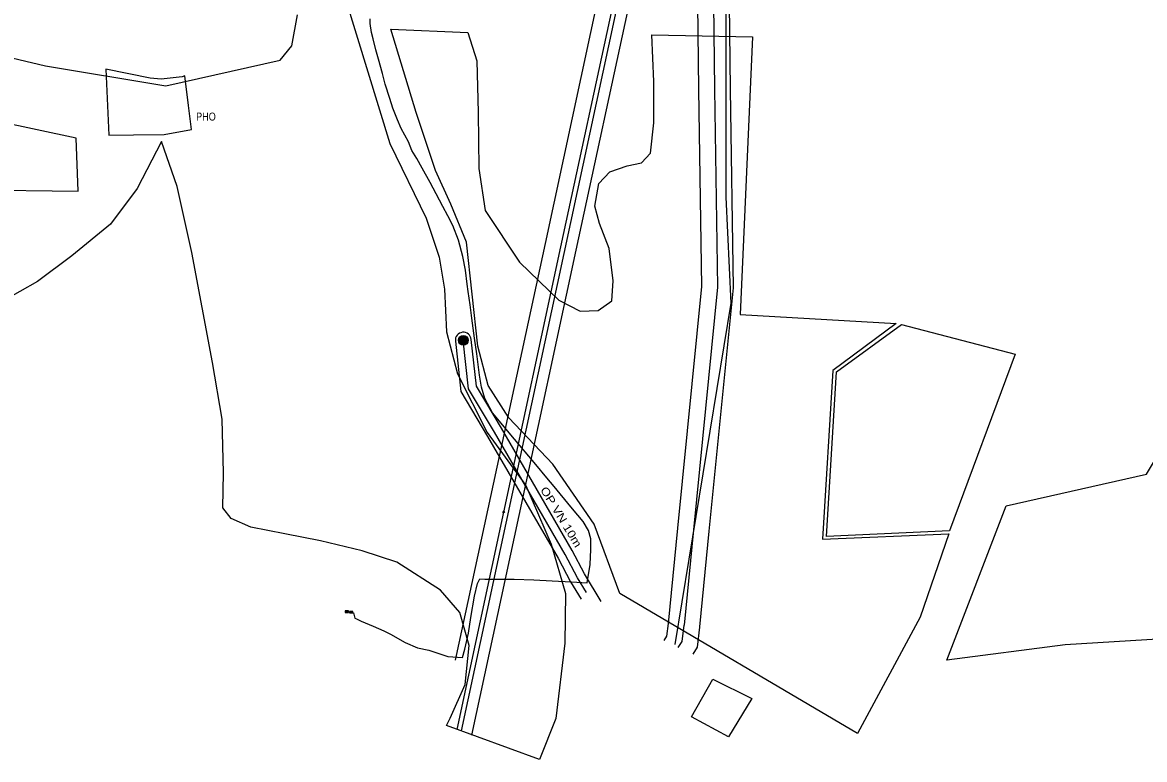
# Model space of a CAD drawing. Extents: x -589836 to -586542, y -1119607 to -1116793.
# Drawn here: x -589106 to -587705, y -1119607 to -1118686 of the extents above; entities that cross this region are included whole.
import ezdxf

# ---------------------------------------------------------------- set-up
doc = ezdxf.new("R2010")
doc.units = 0
doc.header["$LTSCALE"] = 4
doc.header["$PDMODE"] = 32
doc.header["$PDSIZE"] = 2
for name, color, linetype, lineweight in [('18', 7, 'Continuous', 25), ('21', 7, 'Continuous', 25), ('22', 7, 'Continuous', 25), ('25', 7, 'Continuous', 25), ('26', 7, 'Continuous', 25), ('28', 7, 'Continuous', 25), ('29', 7, 'Continuous', 25), ('41', 7, 'Continuous', 25), ('45', 7, 'Continuous', 25)]:
    doc.layers.add(name, color=color, linetype=linetype, lineweight=lineweight)

msp = doc.modelspace()

# ---------------------------------------------------------------- hatches: boundary and pattern name
at = {"layer": '29'}
for points in [[(-588549.665, -1119083.315, 1), (-588561.739, -1119083.315, 1)], [(-588702.105, -1119421.108), (-588700.203, -1119421.108), (-588700.203, -1119423.123), (-588702.105, -1119423.123)], [(-588696.287, -1119421.78), (-588694.385, -1119421.78), (-588694.385, -1119423.795), (-588696.287, -1119423.795)]]:
    msp.add_hatch(color=256, dxfattribs=at).paths.add_polyline_path(points)

# ---------------------------------------------------------------- linework, layer by layer
at = {"layer": '18'}
msp.add_lwpolyline([(-588967.596, -1118826.861), (-588929.401, -1118826.454), (-588895.311, -1118819.858), (-588898.812, -1118790.103), (-588903.367, -1118753.227), (-588906.955, -1118754.484), (-588932.966, -1118756.996), (-588946.958, -1118755.74), (-589002.286, -1118744.685), (-588998.251, -1118827.187)], close=True, dxfattribs=at)
at = {"layer": '21'}
for points in [[(-587457.391, -1116891.203), (-587467.495, -1116906.128), (-587678.431, -1117217.658), (-587869.495, -1117499.964), (-588057.978, -1117778.27), (-588234.704, -1118039.283), (-588299.251, -1118339.426), (-588366.538, -1118652.377), (-588434.124, -1118966.627), (-588505.333, -1119297.805), (-588563.874, -1119569.266)], [(-588222.732, -1117991.024), (-588240.555, -1118139.541), (-588249.547, -1118212.86), (-588245.083, -1118520.625), (-588241.831, -1118769.889), (-588238.396, -1119016.784), (-588268.401, -1119319.835), (-588280.072, -1119439.07)], [(-588401.889, -1119398.315), (-588413.054, -1119379.796), (-588428.514, -1119350.663), (-588516.693, -1119198.167), (-588549.117, -1119143.934), (-588555.689, -1119083.288)], [(-588287.331, -1119467.11), (-588282.404, -1119459.508), (-588280.072, -1119439.07)]]:
    msp.add_lwpolyline(points, dxfattribs=at)
at = {"layer": '22'}
for points in [[(-588260.167, -1119441.018), (-588248.497, -1119321.794), (-588218.382, -1119017.633), (-588221.833, -1118769.619), (-588225.085, -1118520.35), (-588229.529, -1118213.937), (-588220.701, -1118141.95), (-588202.874, -1117993.407)], [(-588246.811, -1118021.492), (-588253.441, -1118031.284), (-588318.804, -1118335.221), (-588386.091, -1118648.172), (-588453.677, -1118962.422), (-588524.885, -1119293.595), (-588565.713, -1119482.918)], [(-588544.923, -1119576.263), (-588485.781, -1119302.015), (-588414.571, -1118970.832), (-588346.985, -1118656.582), (-588279.698, -1118343.631), (-588269.092, -1118294.315)], [(-588268.388, -1118292.891), (-588265.081, -1118520.9), (-588261.829, -1118770.159), (-588258.41, -1119015.935), (-588288.305, -1119317.876), (-588299.977, -1119437.122)], [(-588383.456, -1119409.521), (-588404.349, -1119374.867), (-588419.766, -1119345.815), (-588508.073, -1119193.098), (-588539.411, -1119140.681), (-588545.747, -1119082.211)], [(-588565.631, -1119084.365), (-588558.823, -1119147.187), (-588525.313, -1119203.236), (-588437.262, -1119355.511), (-588421.759, -1119384.725), (-588408.653, -1119406.464)], [(-588299.943, -1119436.803), (-588301.742, -1119452.573), (-588305.464, -1119458.317)], [(-588268.791, -1119475.277), (-588263.066, -1119466.443), (-588260.201, -1119441.337)]]:
    msp.add_lwpolyline(points, dxfattribs=at)
msp.add_arc((-588555.689, -1119083.288), 10, 6.18264, 186.18264, dxfattribs=at)
at = {"layer": '25'}
msp.add_lwpolyline([(-587453.687, -1116893.154), (-588229.609, -1118041.457), (-588558.571, -1119570.952)], dxfattribs=at)
at = {"layer": '26'}
msp.add_lwpolyline([(-588693.26, -1119423.62), (-588692.8, -1119423.53), (-588691.3, -1119430.3), (-588689.26, -1119431.22), (-588683.17, -1119433.96), (-588668.31, -1119440.47), (-588654.85, -1119446.03), (-588646.74, -1119450.41), (-588628.21, -1119460.68), (-588613.09, -1119467.49), (-588598.64, -1119470.05), (-588575, -1119478), (-588556.66, -1119479.54), (-588553.91, -1119469.06), (-588549.35, -1119449.22), (-588546.41, -1119429.3), (-588541.75, -1119402.8), (-588537.92, -1119387.07), (-588535.18, -1119381.34), (-588528.69, -1119381.52), (-588516.84, -1119381.44), (-588492.12, -1119381.56), (-588467.64, -1119382.47), (-588444.55, -1119383.85), (-588420.73, -1119384.88), (-588400.93, -1119386.31), (-588397.47, -1119363.42), (-588396.44, -1119344.44), (-588396.61, -1119331.22), (-588399.18, -1119320.84), (-588405.89, -1119309.42), (-588419.19, -1119293.72), (-588444.46, -1119263.25), (-588449.18, -1119257.64), (-588467.15, -1119236.1), (-588491.89, -1119206.56), (-588519.16, -1119173.98), (-588528.89, -1119156.11), (-588533.11, -1119141.77), (-588535.39, -1119126.68), (-588538.71, -1119100.28), (-588541.72, -1119080.76), (-588545.08, -1119055.45), (-588547.09, -1119039.14), (-588549.46, -1119022.37), (-588550.92, -1119013.06), (-588553, -1118995.85), (-588556.5, -1118978.44), (-588561.81, -1118958.38), (-588568.96, -1118939.87), (-588574.89, -1118927.96), (-588581.25, -1118916.23), (-588589.8, -1118900.37), (-588597.3, -1118886.03), (-588607.11, -1118868.2), (-588613.89, -1118856.25), (-588619.87, -1118846.11), (-588624.08, -1118835.53), (-588633.35, -1118818.97), (-588637.94, -1118808.18), (-588643.62, -1118793.34), (-588647.63, -1118781.51), (-588653.31, -1118763.48), (-588656.69, -1118750.17), (-588661.53, -1118732.2), (-588665.17, -1118720.57), (-588668.5, -1118706.99), (-588670.29, -1118699.03), (-588671.97, -1118687.72), (-588671.94, -1118682.03)], dxfattribs=at)
for points in [[(-588703.29, -1119423.14), (-588699.29, -1119423.14), (-588699.29, -1119421.14), (-588703.29, -1119421.14)], [(-588697.73, -1119423.79), (-588693.73, -1119423.79), (-588693.73, -1119421.79), (-588697.73, -1119421.79)]]:
    msp.add_lwpolyline(points, close=True, dxfattribs=at)
at = {"layer": '28'}
msp.add_point((-588505.333, -1119297.805), dxfattribs=at)
at = {"layer": '29'}
for points in [[(-588702.105, -1119421.108), (-588700.203, -1119421.108), (-588700.203, -1119423.123), (-588702.105, -1119423.123)], [(-588696.287, -1119421.78), (-588694.385, -1119421.78), (-588694.385, -1119423.795), (-588696.287, -1119423.795)]]:
    msp.add_lwpolyline(points, close=True, dxfattribs=at)
msp.add_circle((-588555.702, -1119083.315), 6.037, dxfattribs=at)
at = {"layer": '41'}
msp.add_lwpolyline([(-588441.71, -1117474.54), (-588446.09, -1117528.74), (-588444.76, -1117558.39), (-588437.14, -1117857.91), (-588248.114, -1118205.264), (-588244.69, -1118228.95), (-588227.86, -1118568.33), (-588227.89, -1118904.6), (-588221.46, -1119036.99), (-588291.581, -1119463.13)], dxfattribs=at)
at = {"layer": '45'}
for points in [[(-588702.65, -1118658.663), (-588647.591, -1118837.676), (-588601.996, -1118930.626), (-588586.08, -1118979.682), (-588579.198, -1119019.271), (-588576.617, -1119072.631), (-588562.852, -1119125.13), (-588525.86, -1119198.285), (-588477.684, -1119264.554), (-588445.853, -1119337.709), (-588428.218, -1119399.675), (-588429.078, -1119461.642), (-588440.262, -1119555.452), (-588460.564, -1119606.853), (-588576.781, -1119564.249), (-588572.101, -1119555.023), (-588553.605, -1119513.282), (-588548.443, -1119464.226), (-588560.057, -1119423.345), (-588584.145, -1119395.374), (-588638.774, -1119360.518), (-588682.003, -1119346.317), (-588734.05, -1119333.837), (-588778.785, -1119324.801), (-588820.939, -1119316.624), (-588845.458, -1119305.866), (-588856.211, -1119292.527), (-588855.351, -1119248.634), (-588857.072, -1119181.934), (-588869.116, -1119110.931), (-588894.924, -1118973.659), (-588912.99, -1118891.037), (-588932.777, -1118835.096), (-588962.887, -1118893.619), (-588996.438, -1118938.373), (-589044.615, -1118977.962), (-589087.629, -1119009.806), (-589131.504, -1119034.764)], [(-589209.36, -1118709.441), (-589077.736, -1118740.424), (-588927.185, -1118765.382), (-588784.377, -1118733.539), (-588769.752, -1118715.465), (-588762.87, -1118676.736)], [(-589167.636, -1118895.341), (-589036.872, -1118897.062), (-589039.453, -1118830.793), (-589137.096, -1118810.136)]]:
    msp.add_lwpolyline(points, dxfattribs=at)
for points in [[(-588436.39, -1119033.042), (-588409.721, -1119046.812), (-588387.354, -1119045.952), (-588370.148, -1119033.903), (-588368.427, -1119008.944), (-588373.589, -1118968.494), (-588385.633, -1118937.511), (-588391.655, -1118915.995), (-588386.493, -1118887.594), (-588372.729, -1118872.963), (-588351.222, -1118865.217), (-588333.155, -1118861.774), (-588321.972, -1118849.725), (-588317.67, -1118811.857), (-588317.67, -1118760.219), (-588320.251, -1118701.695), (-588194.649, -1118704.277), (-588210.134, -1119051.116), (-588015.278, -1119062.303), (-588093.994, -1119120.826), (-588106.899, -1119331.684), (-587949.466, -1119324.798), (-587985.168, -1119428.936), (-588063.454, -1119574.386), (-588360.254, -1119399.675), (-588392.085, -1119312.751), (-588443.702, -1119237.875), (-588498.761, -1119180.212), (-588524.569, -1119139.762), (-588537.474, -1119090.705), (-588551.669, -1118960.748), (-588571.456, -1118913.413), (-588590.382, -1118871.241), (-588614.47, -1118798.948), (-588646.301, -1118694.81), (-588549.948, -1118699.113), (-588538.765, -1118734.399), (-588537.044, -1118798.948), (-588536.184, -1118868.66), (-588528.441, -1118921.159), (-588485.427, -1118985.707)], [(-586823.13, -1118881.984), (-586814.527, -1118997.31), (-587119.07, -1118961.163), (-587458.025, -1119114.357), (-587452.863, -1119196.979), (-587347.908, -1119172.881), (-587175.85, -1119258.945), (-587162.085, -1119393.206), (-587337.584, -1119434.517), (-587525.128, -1119446.566), (-587803.862, -1119463.779), (-587951.832, -1119482.713), (-587877.847, -1119289.929), (-587702.348, -1119250.339), (-587681.701, -1119215.913), (-587676.539, -1119153.947), (-587690.304, -1119074.768), (-587134.556, -1118890.59), (-586895.395, -1118897.475)], [(-587948.605, -1119321.34), (-588102.167, -1119328.225), (-588089.693, -1119122.532), (-588008.611, -1119063.578), (-587866.663, -1119100.585)], [(-588224.581, -1119578.45), (-588270.713, -1119553.598), (-588244.098, -1119506.556), (-588195.305, -1119530.521)]]:
    msp.add_lwpolyline(points, close=True, dxfattribs=at)

# ---------------------------------------------------------------- texts
at = {"layer": '18', "width": 0.85}
msp.add_text('PHO', height=10, dxfattribs=at).set_placement((-588889.455, -1118808.94))
at = {"layer": '22', "width": 1.2}
msp.add_text('OP VN 10m', height=10, rotation=301.254, dxfattribs=at).set_placement((-588459.978, -1119269.924))

doc.saveas('drawing.dxf')
